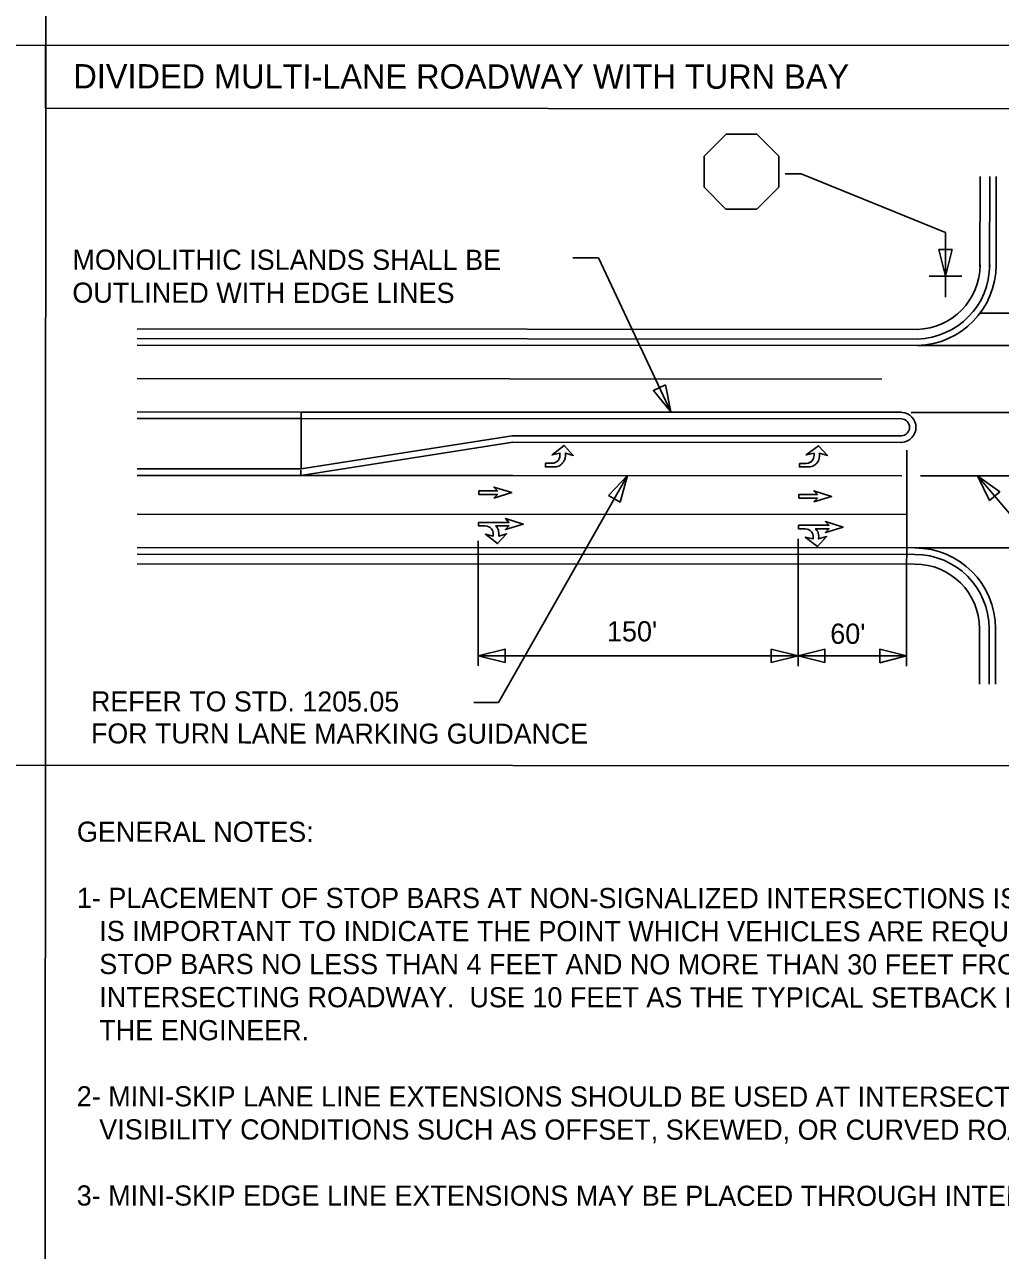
# Model space of a CAD drawing. Extents: x 50667 to 52386, y 46650 to 50479.
# Drawn here: x 51454.8 to 51802.6, y 47063.4 to 47500.4 of the extents above; entities that cross this region are included whole.
import ezdxf

# ---------------------------------------------------------------- set-up
doc = ezdxf.new("R2010")
doc.units = 0
for name, color, linetype in [('Default', 7, 'Continuous'), ('DEV TUBULAR MARKER SECTIONAL VIEW CELL', 7, 'Continuous'), ('Exist Guardrail Text', 7, 'Continuous'), ('Exist Hydro Jurisdictional Stream or Body of Water Text', 7, 'Continuous'), ('Exist Hydro Spring CELL', 7, 'Continuous'), ('Exist Hydro Spring Leader', 7, 'Continuous'), ('Exist Hydro Spring Text', 7, 'Continuous'), ('Exist Utilities Telephone Pole Text Tag Number', 7, 'Continuous'), ('Gray Area Fill Shapes', 7, 'Continuous'), ('Matchline', 7, 'Continuous'), ('Old_Level_49', 7, 'Continuous'), ('Prop EOT Dash', 7, 'Continuous'), ('Prop SBG', 7, 'Continuous'), ('Sheet North Arrow CELL', 7, 'Continuous')]:
    doc.layers.add(name, color=color, linetype=linetype)

msp = doc.modelspace()

# ---------------------------------------------------------------- linework, layer by layer
at = {"layer": 'Default'}
for p, q in [((51462.45, 47676.12), (51462.09, 46906.44)), ((52075.53, 47492.74), (50973.75, 47493.26)), ((51696.98, 47453.43), (51704.8, 47461.24)), ((51704.8, 47461.24), (51715.82, 47461.24)), ((51715.82, 47461.24), (51723.67, 47453.42)), ((51696.98, 47442.37), (51696.98, 47453.43)), ((51723.67, 47453.42), (51723.67, 47442.35)), ((51725.87, 47447.1), (51731.62, 47447.09)), ((51783.02, 47426.21), (51731.62, 47447.09)), ((51704.78, 47434.55), (51696.98, 47442.37)), ((51723.67, 47442.35), (51715.8, 47434.55)), ((51715.8, 47434.55), (51704.78, 47434.55)), ((51783.02, 47410.69), (51783.02, 47426.21)), ((51650.22, 47417.17), (51659.39, 47417.17)), ((51659.39, 47417.17), (51685.12, 47362.3)), ((51795.28, 47397.45), (51815.69, 47397.44)), ((51553.15, 47362.23), (51495.01, 47362.25)), ((51767.35, 47362.13), (51553.36, 47362.23)), ((51553.18, 47359.93), (51495.01, 47359.95)), ((51553.36, 47341.96), (51553.36, 47359.93)), ((51553.36, 47359.93), (51767.35, 47359.83)), ((51628.61, 47353.79), (51553.36, 47341.96)), ((51767.33, 47353.72), (51628.61, 47353.79)), ((51628.79, 47351.49), (51553.35, 47339.63)), ((51767.33, 47351.42), (51628.61, 47351.49)), ((51769.14, 47271.68), (51769.18, 47348.7)), ((51623.77, 47258.66), (51669.66, 47339.58)), ((51861.63, 47260.23), (51794.41, 47339.52)), ((51730.47, 47271.69), (51730.5, 47317.08)), ((51616.48, 47271.75), (51616.5, 47316.32)), ((51795.08, 47285.05), (51795.07, 47265.23)), ((51798.53, 47285.05), (51798.52, 47265.23)), ((51800.83, 47285.04), (51800.82, 47265.23)), ((51616.48, 47275.35), (51730.43, 47275.3)), ((51730.48, 47275.3), (51769.14, 47275.28)), ((51614.98, 47258.66), (51623.77, 47258.66)), ((52075.41, 47236.01), (50973.63, 47236.53))]:
    msp.add_line(p, q, dxfattribs=at)
for centre, radius, start, end in [((51772.3, 47414.7), 23, 271.4528, 359.9734), ((51772.3, 47414.7), 26.45, 271.4528, 359.9734), ((51772.3, 47414.7), 28.75, 271.4528, 359.9734), ((51767.12, 47356.77), 5.36, 273.8782, 86.0687), ((51767.12, 47356.77), 3.06, 273.8782, 86.0687), ((51772.09, 47285.05), 28.75, 359.9734, 89.9734), ((51772.09, 47285.05), 26.45, 359.9734, 89.9734), ((51772.09, 47285.05), 23, 359.9734, 89.9734)]:
    msp.add_arc(centre, radius, start, end, dxfattribs=at)
at = {"layer": 'DEV TUBULAR MARKER SECTIONAL VIEW CELL'}
msp.add_lwpolyline([(51462.35, 47470.51), (51820.66, 47470.34), (51820.67, 47492.86), (51462.36, 47493.03)], close=True, dxfattribs=at)
at = {"layer": 'Exist Guardrail Text'}
for p, q in [((51788.88, 47410.68), (51777.24, 47410.69)), ((51783.02, 47410.69), (51783.01, 47403.14))]:
    msp.add_line(p, q, dxfattribs=at)
at = {"layer": 'Exist Hydro Jurisdictional Stream or Body of Water Text'}
msp.add_line((51628.79, 47339.6), (51553.35, 47339.63), dxfattribs=at)
at = {"layer": 'Exist Hydro Spring CELL'}
for p, q in [((51553.36, 47341.96), (51553.36, 47359.93)), ((51553.36, 47359.93), (51767.35, 47359.83)), ((51628.61, 47353.79), (51553.36, 47341.96)), ((51767.33, 47353.72), (51628.61, 47353.79))]:
    msp.add_line(p, q, dxfattribs=at)
msp.add_arc((51767.12, 47356.77), 3.06, 273.8782, 86.0687, dxfattribs=at)
at = {"layer": 'Exist Hydro Spring Leader'}
msp.add_line((51770.73, 47362.1), (51860.55, 47362.06), dxfattribs=at)
at = {"layer": 'Exist Hydro Spring Text'}
for p, q in [((51773.03, 47385.96), (51856.64, 47385.92)), ((51774.15, 47339.53), (51859.91, 47339.49)), ((51772.11, 47313.8), (51861.02, 47313.76))]:
    msp.add_line(p, q, dxfattribs=at)
at = {"layer": 'Exist Utilities Telephone Pole Text Tag Number'}
for p, q in [((51495.01, 47374.13), (51760.33, 47374)), ((51494.98, 47325.82), (51769.17, 47325.7))]:
    msp.add_line(p, q, dxfattribs=at)
at = {"layer": 'Gray Area Fill Shapes'}
for p, q in [((51795.3, 47446.17), (51795.29, 47413.97)), ((51798.75, 47446.17), (51798.74, 47413.97)), ((51801.05, 47446.17), (51801.04, 47413.97)), ((51553.36, 47360), (51553.36, 47362.23)), ((51553.36, 47341.93), (51495, 47341.96)), ((51553.24, 47339.63), (51495, 47339.66)), ((51553.35, 47339.63), (51553.35, 47341.49)), ((51628.79, 47339.6), (51767.39, 47339.53))]:
    msp.add_line(p, q, dxfattribs=at)
at = {"layer": 'Matchline'}
for points in [[(51616.66, 47322.91), (51627.46, 47322.9), (51626.22, 47324.25), (51632.55, 47322.28), (51626.21, 47320.31), (51627.46, 47321.66), (51622.76, 47321.66), (51623.22, 47321.09), (51623.47, 47320.65), (51623.67, 47320.09), (51623.77, 47319.63), (51623.85, 47319.05), (51623.82, 47318.03), (51626.63, 47318.86), (51623.41, 47315.33), (51619.05, 47318.65), (51621.85, 47318.03), (51621.84, 47318.84), (51621.82, 47319.31), (51621.7, 47319.79), (51621.48, 47320.21), (51621.24, 47320.63), (51620.8, 47321.05), (51620.26, 47321.37), (51619.68, 47321.57), (51619.03, 47321.67), (51616.66, 47321.66)], [(51616.66, 47322.91), (51627.46, 47322.9), (51626.22, 47324.25), (51632.55, 47322.28), (51626.21, 47320.31), (51627.46, 47321.66), (51622.76, 47321.66), (51623.22, 47321.09), (51623.47, 47320.65), (51623.67, 47320.09), (51623.77, 47319.63), (51623.85, 47319.05), (51623.82, 47318.03), (51626.63, 47318.86), (51623.41, 47315.33), (51619.05, 47318.65), (51621.85, 47318.03), (51621.84, 47318.84), (51621.82, 47319.31), (51621.7, 47319.79), (51621.48, 47320.21), (51621.24, 47320.63), (51620.8, 47321.05), (51620.26, 47321.37), (51619.68, 47321.57), (51619.03, 47321.67), (51616.66, 47321.66)], [(51730.64, 47321.86), (51741.44, 47321.86), (51740.2, 47323.21), (51746.53, 47321.23), (51740.19, 47319.26), (51741.44, 47320.61), (51736.74, 47320.61), (51737.2, 47320.04), (51737.46, 47319.6), (51737.65, 47319.04), (51737.75, 47318.59), (51737.83, 47318.01), (51737.81, 47316.98), (51740.61, 47317.81), (51737.39, 47314.28), (51733.03, 47317.6), (51735.83, 47316.98), (51735.82, 47317.79), (51735.8, 47318.27), (51735.68, 47318.75), (51735.46, 47319.16), (51735.22, 47319.58), (51734.78, 47320), (51734.24, 47320.32), (51733.66, 47320.52), (51733.01, 47320.62), (51730.64, 47320.62)], [(51730.64, 47321.86), (51741.44, 47321.86), (51740.2, 47323.21), (51746.53, 47321.23), (51740.19, 47319.26), (51741.44, 47320.61), (51736.74, 47320.61), (51737.2, 47320.04), (51737.46, 47319.6), (51737.65, 47319.04), (51737.75, 47318.59), (51737.83, 47318.01), (51737.81, 47316.98), (51740.61, 47317.81), (51737.39, 47314.28), (51733.03, 47317.6), (51735.83, 47316.98), (51735.82, 47317.79), (51735.8, 47318.27), (51735.68, 47318.75), (51735.46, 47319.16), (51735.22, 47319.58), (51734.78, 47320), (51734.24, 47320.32), (51733.66, 47320.52), (51733.01, 47320.62), (51730.64, 47320.62)]]:
    msp.add_lwpolyline(points, close=True, dxfattribs=at)
at = {"layer": 'Old_Level_49'}
for p, q in [((51495.03, 47391.84), (51773.03, 47391.71)), ((51495.02, 47388.39), (51773.03, 47388.26)), ((51495.02, 47386.09), (51773.03, 47385.96)), ((51494.99, 47313.93), (51772.11, 47313.8)), ((51494.99, 47311.63), (51772.1, 47311.5)), ((51494.99, 47308.18), (51772.1, 47308.05))]:
    msp.add_line(p, q, dxfattribs=at)
at = {"layer": 'Prop EOT Dash'}
for points in [[(51785.39, 47420.17), (51783.02, 47410.69), (51780.65, 47420.18)], [(51785.39, 47420.17), (51783.02, 47410.69), (51780.65, 47420.18)], [(51683.24, 47371.9), (51685.12, 47362.3), (51678.94, 47369.88)], [(51683.24, 47371.9), (51685.12, 47362.3), (51678.94, 47369.88)], [(51662.92, 47332.49), (51669.66, 47339.58), (51667.04, 47330.15)], [(51662.92, 47332.49), (51669.66, 47339.58), (51667.04, 47330.15)], [(51798.74, 47330.75), (51794.41, 47339.52), (51802.36, 47333.82)], [(51798.74, 47330.75), (51794.41, 47339.52), (51802.36, 47333.82)], [(51626.07, 47272.95), (51616.48, 47275.35), (51626.07, 47277.74)], [(51626.07, 47272.95), (51616.48, 47275.35), (51626.07, 47277.74)], [(51720.89, 47272.91), (51730.48, 47275.3), (51720.89, 47277.7)], [(51720.89, 47272.91), (51730.48, 47275.3), (51720.89, 47277.7)], [(51740.06, 47272.9), (51730.48, 47275.3), (51740.06, 47277.69)], [(51740.06, 47272.9), (51730.48, 47275.3), (51740.06, 47277.69)], [(51759.56, 47272.89), (51769.14, 47275.28), (51759.56, 47277.68)], [(51759.56, 47272.89), (51769.14, 47275.28), (51759.56, 47277.68)]]:
    msp.add_lwpolyline(points, close=True, dxfattribs=at)
at = {"layer": 'Prop SBG'}
for points in [[(51640.42, 47343.95), (51640.42, 47342.7), (51643.64, 47342.7), (51644.23, 47342.73), (51644.69, 47342.81), (51645.18, 47342.97), (51645.59, 47343.19), (51645.9, 47343.4), (51646.31, 47343.75), (51646.59, 47344.07), (51646.88, 47344.44), (51647.18, 47344.93), (51647.34, 47345.32), (51647.49, 47345.85), (51647.59, 47346.58), (51647.59, 47347.58), (51650.39, 47346.75), (51647.17, 47350.28), (51642.81, 47346.96), (51645.62, 47347.58), (51645.62, 47346.75), (51645.59, 47346.28), (51645.47, 47345.85), (51645.31, 47345.52), (51645.06, 47345.09), (51644.82, 47344.79), (51644.41, 47344.46), (51643.94, 47344.23), (51643.47, 47344.05), (51642.81, 47343.95)], [(51640.42, 47343.95), (51640.42, 47342.71), (51643.64, 47342.7), (51644.23, 47342.74), (51644.68, 47342.81), (51645.18, 47342.97), (51645.59, 47343.19), (51645.9, 47343.4), (51646.31, 47343.76), (51646.59, 47344.07), (51646.88, 47344.44), (51647.18, 47344.93), (51647.33, 47345.32), (51647.49, 47345.85), (51647.59, 47346.58), (51647.59, 47347.58), (51650.39, 47346.75), (51647.17, 47350.28), (51642.81, 47346.96), (51645.61, 47347.58), (51645.61, 47346.75), (51645.59, 47346.29), (51645.47, 47345.85), (51645.31, 47345.52), (51645.06, 47345.09), (51644.82, 47344.79), (51644.41, 47344.46), (51643.94, 47344.23), (51643.47, 47344.05), (51642.81, 47343.95)], [(51730.96, 47343.91), (51730.96, 47342.66), (51734.18, 47342.66), (51734.77, 47342.69), (51735.22, 47342.77), (51735.71, 47342.93), (51736.13, 47343.14), (51736.44, 47343.36), (51736.85, 47343.71), (51737.13, 47344.03), (51737.42, 47344.4), (51737.72, 47344.89), (51737.87, 47345.28), (51738.03, 47345.81), (51738.13, 47346.54), (51738.13, 47347.54), (51740.93, 47346.71), (51737.71, 47350.24), (51733.35, 47346.92), (51736.15, 47347.54), (51736.15, 47346.71), (51736.13, 47346.24), (51736.01, 47345.81), (51735.85, 47345.48), (51735.6, 47345.05), (51735.36, 47344.75), (51734.95, 47344.42), (51734.48, 47344.18), (51734.01, 47344.01), (51733.35, 47343.91)], [(51730.96, 47343.91), (51730.96, 47342.66), (51734.18, 47342.66), (51734.77, 47342.69), (51735.22, 47342.77), (51735.71, 47342.93), (51736.13, 47343.14), (51736.44, 47343.36), (51736.85, 47343.71), (51737.13, 47344.03), (51737.42, 47344.4), (51737.72, 47344.89), (51737.87, 47345.28), (51738.03, 47345.81), (51738.13, 47346.54), (51738.13, 47347.54), (51740.93, 47346.71), (51737.71, 47350.24), (51733.35, 47346.92), (51736.15, 47347.54), (51736.15, 47346.71), (51736.13, 47346.24), (51736.01, 47345.81), (51735.85, 47345.48), (51735.6, 47345.05), (51735.36, 47344.75), (51734.95, 47344.42), (51734.48, 47344.19), (51734.01, 47344.01), (51733.35, 47343.91)]]:
    msp.add_lwpolyline(points, close=True, dxfattribs=at)
at = {"layer": 'Sheet North Arrow CELL'}
for points in [[(51622.08, 47331.53), (51623.33, 47332.88), (51616.68, 47332.88), (51616.68, 47334.13), (51623.33, 47334.13), (51622.08, 47335.48), (51628.42, 47333.5)], [(51622.08, 47331.53), (51623.33, 47332.88), (51616.68, 47332.88), (51616.68, 47334.13), (51623.33, 47334.13), (51622.08, 47335.48), (51628.42, 47333.5)], [(51736.1, 47330.2), (51737.34, 47331.55), (51730.7, 47331.55), (51730.7, 47332.8), (51737.35, 47332.8), (51736.1, 47334.15), (51742.43, 47332.17)], [(51736.1, 47330.2), (51737.34, 47331.55), (51730.7, 47331.55), (51730.7, 47332.8), (51737.35, 47332.8), (51736.1, 47334.15), (51742.43, 47332.17)]]:
    msp.add_lwpolyline(points, close=True, dxfattribs=at)

# ---------------------------------------------------------------- texts
at = {"layer": 'Default'}
for s, height, p in [('DIVIDED MULTI-LANE ROADWAY WITH TURN BAY', 8.652, (51472.24, 47477.59)), ('MONOLITHIC ISLANDS SHALL BE ', 7.1874, (51471.9, 47412.96)), ('OUTLINED WITH EDGE LINES', 7.1874, (51471.89, 47401.18)), ("150'", 7.187, (51662.38, 47280.49)), ("60'", 7.187, (51741.94, 47279.63)), ('GENERAL NOTES:', 7.1874, (51473.49, 47209.05)), ('1- PLACEMENT OF STOP BARS AT NON-SIGNALIZED INTERSECTIONS IS OPTIONAL AND USED WHERE IT', 7.1874, (51473.48, 47185.48)), ('   IS IMPORTANT TO INDICATE THE POINT WHICH VEHICLES ARE REQUIRED TO STOP.  PLACE ', 7.1874, (51473.47, 47173.69)), ('   STOP BARS NO LESS THAN 4 FEET AND NO MORE THAN 30 FEET FROM THE NEAREST EDGE OF THE', 7.1874, (51473.47, 47161.9)), ('   INTERSECTING ROADWAY.  USE 10 FEET AS THE TYPICAL SETBACK DISTANCE OR AS DIRECTED BY', 7.1874, (51473.46, 47150.11)), ('   THE ENGINEER.', 7.1874, (51473.45, 47138.33)), ('2- MINI-SKIP LANE LINE EXTENSIONS SHOULD BE USED AT INTERSECTIONS THAT HAVE REDUCED', 7.1874, (51473.44, 47114.75)), ('   VISIBILITY CONDITIONS SUCH AS OFFSET, SKEWED, OR CURVED ROADWAYS.', 7.1874, (51473.44, 47102.96)), ('3- MINI-SKIP EDGE LINE EXTENSIONS MAY BE PLACED THROUGH INTERSECTIONS AND MAJOR DRIVEWAYS.', 7.1874, (51473.43, 47079.39))]:
    msp.add_text(s, height=height, rotation=359.9734, dxfattribs=at).set_placement(p)
at = {"layer": 'Old_Level_49'}
for s, p in [('REFER TO STD. 1205.05', (51478.54, 47255.53)), ('FOR TURN LANE MARKING GUIDANCE', (51478.53, 47244.11))]:
    msp.add_text(s, height=7.138, rotation=359.9734, dxfattribs=at).set_placement(p)

doc.saveas('drawing.dxf')
